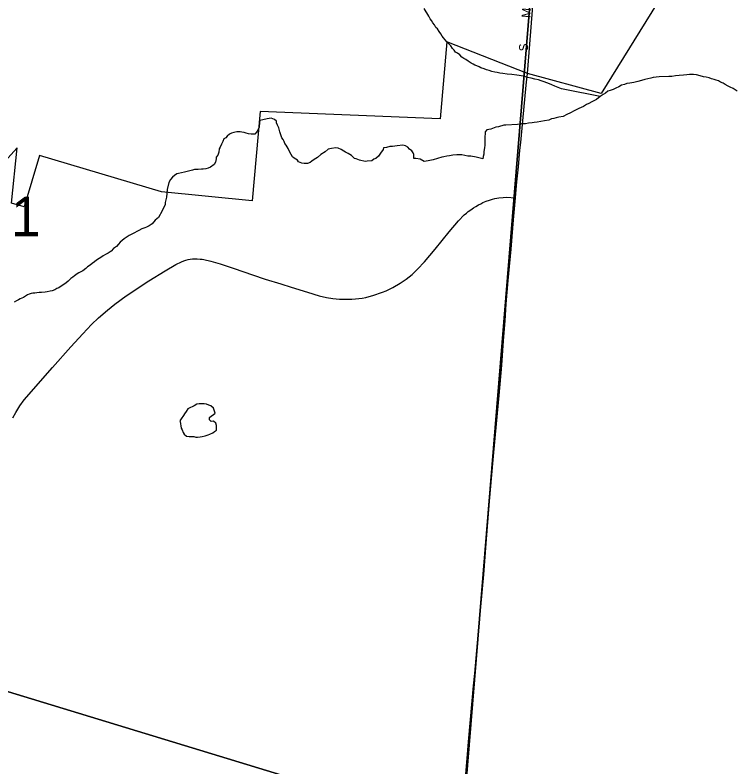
# Model space of a CAD drawing. Extents: x 1410790 to 1770854, y 448063 to 770588.
# Drawn here: x 1523133 to 1527172, y 593947 to 598152 of the extents above; entities that cross this region are included whole.
import ezdxf

# ---------------------------------------------------------------- set-up
doc = ezdxf.new("R2010")
doc.units = 0
for name, color, linetype in [('GM_X_City_Street', 7, 'Continuous'), ('GM_X_City_Street_Text', 7, 'Continuous'), ('GM_X_Corporation', 7, 'Continuous'), ('GM_X_County_Road', 7, 'Continuous'), ('GM_X_Minor_Lake', 7, 'Continuous'), ('GM_X_Minor_River', 7, 'Continuous'), ('GM_X_Section', 7, 'Continuous'), ('GM_X_Section_Text', 7, 'Continuous'), ('GM_X_Township_Road', 7, 'Continuous')]:
    doc.layers.add(name, color=color, linetype=linetype)

msp = doc.modelspace()

# ---------------------------------------------------------------- linework, layer by layer
at = {"layer": 'GM_X_City_Street'}
msp.add_lwpolyline([(1525999.4, 597825.8), (1526012.8, 597989), (1526020.3, 598085), (1526040.1, 598323.6), (1526064.5, 598621), (1526066.6, 598648.9)], dxfattribs=at)
at = {"layer": 'GM_X_Corporation'}
msp.add_lwpolyline([(1526753.1, 598265.5), (1526412.1, 597713.3), (1525999.4, 597825.8), (1525548.4, 598001.8), (1525512.3, 597571.6), (1524504.8, 597611.8), (1524459.5, 597113.5), (1523951.6, 597163.7), (1523269.7, 597366.5), (1523184.4, 597079.5), (1523113.2, 597100.8), (1523145.6, 597408.8), (1522880.8, 597121.1)], dxfattribs=at)
at = {"layer": 'GM_X_County_Road'}
for points in [[(1525932.9, 597129.9), (1525940.9, 597218.9), (1525949.3, 597303.2), (1525958, 597397.2), (1525962.1, 597438.9), (1525973.6, 597560.6), (1525993, 597759.4), (1525999.4, 597825.8)], [(1525646.9, 593818.8), (1525661.1, 593972.3), (1525671.1, 594086.5), (1525698.6, 594400.2), (1525705.4, 594468.7), (1525721.3, 594641.8), (1525756.5, 595023.8), (1525768.7, 595196.7), (1525788.5, 595432.4), (1525807.9, 595664.4), (1525818.5, 595785.3), (1525831.8, 595925.7), (1525841.6, 596023.3), (1525856.7, 596193.8), (1525866.9, 596330.6), (1525875.1, 596441.7), (1525881.6, 596536.5), (1525892, 596667.2), (1525908.2, 596843.1), (1525922.3, 597006.5), (1525932.9, 597129.9)]]:
    msp.add_lwpolyline(points, dxfattribs=at)
at = {"layer": 'GM_X_Minor_Lake'}
msp.add_lwpolyline([(1524063, 595842.4), (1524067.3, 595832.1), (1524073, 595817.9), (1524078.8, 595807.8), (1524092.6, 595797.4), (1524106.6, 595795), (1524118.6, 595794.8), (1524132.6, 595794.4), (1524144.6, 595792.1), (1524154.6, 595791.9), (1524168.6, 595793.5), (1524180.7, 595795.3), (1524196.8, 595798.9), (1524213, 595804.5), (1524223.1, 595808.3), (1524239.3, 595815.9), (1524249.5, 595823.7), (1524259.6, 595829.5), (1524259.9, 595843.5), (1524260.2, 595855.5), (1524256.5, 595869.7), (1524242.7, 595880), (1524230.7, 595878.3), (1524220.9, 595888.5), (1524221.1, 595900.6), (1524231.4, 595910.4), (1524241.5, 595916.1), (1524251.8, 595925.9), (1524242.4, 595954.2), (1524228.6, 595966.6), (1524216.7, 595970.9), (1524204.8, 595975.2), (1524190.8, 595977.5), (1524178.8, 595977.8), (1524162.8, 595978.2), (1524150.7, 595976.5), (1524134.5, 595966.8), (1524124.3, 595961.1), (1524114.2, 595957.3), (1524100, 595949.6), (1524089.7, 595933.8), (1524081.4, 595922), (1524075.1, 595912.1), (1524062.7, 595894.4), (1524054.4, 595882.5), (1524056.4, 595878.5), (1524063, 595842.4)], dxfattribs=at)
at = {"layer": 'GM_X_Minor_River'}
for points in [[(1526406.8, 597696.2), (1526208.9, 597736.4), (1526190.9, 597738.6), (1526180.9, 597742.7), (1526153, 597755), (1526137, 597761.2), (1526123.1, 597767.4), (1526093.1, 597777.7), (1526077.2, 597783.9), (1526061.2, 597790.1), (1526041.2, 597794.3), (1526021.2, 597798.5), (1526001.2, 597802.7), (1525977.3, 597811), (1525941.3, 597815.4), (1525913.3, 597819.7), (1525887.2, 597822), (1525863.2, 597824.2), (1525845.2, 597826.4), (1525831.2, 597830.6), (1525817.2, 597832.7), (1525801.3, 597836.9), (1525785.3, 597841.1), (1525771.3, 597845.2), (1525757.3, 597851.4), (1525739.3, 597857.6), (1525729.4, 597861.7), (1525717.4, 597867.8), (1525705.4, 597872), (1525695.5, 597878.1), (1525685.5, 597882.2), (1525667.6, 597894.4), (1525655.6, 597902.6), (1525643.7, 597908.7), (1525633.7, 597916.8), (1525621.8, 597929), (1525607.9, 597939.2), (1525597.9, 597945.3), (1525590, 597955.4), (1525580.1, 597965.5), (1525572.2, 597979.6), (1525560.3, 597991.8), (1525548.4, 598001.9), (1525540.5, 598014.1), (1525530.5, 598024.2), (1525522.6, 598034.3), (1525514.7, 598046.4), (1525506.8, 598060.5), (1525496.9, 598074.7), (1525487, 598082.8), (1525479.1, 598096.9), (1525471.2, 598109), (1525463.3, 598121.1), (1525455.4, 598131.2), (1525447.5, 598145.4), (1525421.8, 598187.8)], [(1527174.2, 597726.3), (1527150.3, 597740.6), (1527134.3, 597748.8), (1527122.4, 597754.9), (1527106.4, 597763.1), (1527094.5, 597771.3), (1527080.5, 597777.4), (1527068.6, 597783.6), (1527056.6, 597787.7), (1527044.6, 597791.8), (1527030.6, 597796), (1527016.6, 597800.2), (1527000.6, 597804.3), (1526984.6, 597806.5), (1526966.7, 597812.7), (1526946.7, 597816.9), (1526928.7, 597819.1), (1526918.6, 597819.2), (1526906.6, 597819.4), (1526892.6, 597817.5), (1526872.6, 597815.7), (1526848.5, 597813.9), (1526828.5, 597812.2), (1526808.4, 597808.4), (1526790.4, 597808.5), (1526736.3, 597807.1), (1526720.2, 597805.3), (1526704.2, 597803.4), (1526690.2, 597799.6), (1526674.1, 597795.7), (1526656, 597791.9), (1526638, 597786.1), (1526617.9, 597780.3)], [(1526617.9, 597780.3), (1526595.8, 597774.5), (1526573.7, 597770.7), (1526555.7, 597768.9), (1526543.6, 597763), (1526525.6, 597759.2), (1526511.5, 597751.3), (1526495.4, 597743.4), (1526479.3, 597735.6), (1526463.2, 597729.7), (1526449.2, 597725.9), (1526437.1, 597716), (1526423, 597708.1), (1526406.8, 597696.2), (1526386.7, 597680.4), (1526360.5, 597666.6), (1526344.4, 597656.8), (1526330.3, 597650.9), (1526314.2, 597641), (1526300.2, 597635.2), (1526288.1, 597629.3), (1526276, 597623.4), (1526261.9, 597615.5), (1526241.8, 597605.7), (1526219.7, 597595.9), (1526199.6, 597584.1), (1526175.5, 597580.3), (1526161.4, 597576.5), (1526147.4, 597572.6), (1526135.3, 597570.7), (1526119.3, 597564.9), (1526095.2, 597561.1), (1526075.1, 597557.3), (1526055.1, 597553.5), (1526037, 597551.7), (1526027, 597549.8), (1526005, 597548), (1525988.9, 597544.2), (1525966.9, 597544.4), (1525944.8, 597540.6), (1525878.7, 597535.3), (1525868.7, 597535.4), (1525838.5, 597527.7), (1525822.5, 597525.8), (1525794.4, 597514.1), (1525772.3, 597510.3), (1525764.2, 597498.4), (1525764.1, 597486.3), (1525762, 597474.3), (1525761.7, 597446.3), (1525761.5, 597424.2), (1525759.4, 597410.2), (1525757.3, 597400.2), (1525755.2, 597386.2), (1525755.1, 597374.1), (1525752.9, 597360.1), (1525750.8, 597348.1), (1525712.8, 597356.5), (1525682.9, 597362.9), (1525666.8, 597363), (1525632.9, 597369.4), (1525604.8, 597369.7), (1525582.8, 597367.9), (1525564.7, 597364.1), (1525548.7, 597362.2), (1525532.6, 597358.4), (1525520.6, 597356.5), (1525472.4, 597343), (1525444.3, 597337.2), (1525422.2, 597333.5), (1525400.3, 597345.7), (1525376.3, 597350), (1525364.3, 597350.1), (1525364.4, 597362.1), (1525364.5, 597372.2), (1525360.6, 597382.2), (1525352.7, 597392.3), (1525340.7, 597402.5), (1525330.8, 597412.6), (1525316.9, 597420.8), (1525302.9, 597424.9), (1525270.8, 597421.3), (1525244.7, 597417.5), (1525230.7, 597417.7), (1525210.6, 597411.9), (1525194.6, 597410), (1525192.5, 597400), (1525178.3, 597380.1), (1525166.1, 597362.2), (1525152, 597350.3), (1525140, 597346.4), (1525129.9, 597336.5), (1525103.8, 597334.8), (1525091.8, 597332.9), (1525059.8, 597341.2), (1525041.8, 597347.4), (1525031.8, 597349.5), (1525016, 597365.8), (1524996, 597378), (1524982.1, 597384.2), (1524972.1, 597390.3)], [(1524972.1, 597390.3), (1524958.2, 597400.4), (1524940.2, 597406.6), (1524928.2, 597408.8), (1524904.2, 597405), (1524884.1, 597401.2), (1524867.9, 597387.3), (1524843.8, 597371.5), (1524825.6, 597355.7), (1524807.5, 597343.8), (1524793.4, 597334), (1524783.3, 597328.1), (1524769.2, 597322.2), (1524751.2, 597322.4), (1524737.2, 597324.5), (1524719.2, 597330.7), (1524713.3, 597340.8), (1524695.4, 597351), (1524685.4, 597359.2), (1524669.7, 597385.4), (1524661.8, 597405.5), (1524650, 597423.7), (1524642.1, 597433.8), (1524638.1, 597443.9), (1524632.2, 597455.9), (1524626.3, 597466), (1524618.5, 597488.2), (1524614.6, 597498.2), (1524608.8, 597520.4), (1524600.9, 597536.5), (1524595, 597548.6), (1524595.1, 597558.6), (1524585.2, 597568.7), (1524565.2, 597575), (1524543.1, 597571.2), (1524519.1, 597565.4), (1524503, 597561.6), (1524500.9, 597551.6), (1524498.7, 597525.5), (1524490.5, 597507.5), (1524484.4, 597497.6), (1524474.3, 597485.7), (1524454.3, 597485.9), (1524438.3, 597488), (1524426.3, 597492.2), (1524414.3, 597494.3), (1524402.3, 597496.4), (1524392.3, 597498.5), (1524374.3, 597498.7), (1524356.2, 597494.9), (1524344.2, 597491), (1524332.1, 597485.1), (1524320, 597475.2), (1524311.9, 597465.3), (1524301.8, 597459.4), (1524295.7, 597445.4), (1524287.5, 597429.4), (1524281.4, 597413.4), (1524275.3, 597403.5), (1524273.1, 597385.5), (1524266.9, 597367.5), (1524258.8, 597357.5), (1524258.8, 597347.5), (1524254.6, 597329.5), (1524246.5, 597315.5), (1524226.3, 597301.7), (1524214.2, 597295.8), (1524200.2, 597292), (1524186.1, 597290.1), (1524176.1, 597290.2), (1524158.1, 597288.4), (1524136.1, 597288.6), (1524126, 597284.7), (1524103.9, 597278.9), (1524081.8, 597273.1), (1524063.8, 597269.3), (1524047.7, 597265.5), (1524037.7, 597263.6), (1524025.6, 597253.7), (1524013.5, 597245.8), (1524003.4, 597231.8), (1523993.2, 597215.9), (1523984.9, 597175.9), (1523980.5, 597133.8), (1523972.2, 597103.8), (1523972.1, 597091.8), (1523955.8, 597057.8), (1523935.4, 597020), (1523917.2, 597004.1), (1523901, 596984.2), (1523882.9, 596972.4), (1523868.8, 596966.5), (1523858.8, 596962.6), (1523842.7, 596956.8), (1523824.6, 596946.9), (1523814.5, 596941), (1523800.4, 596933.1), (1523790.4, 596929.2), (1523772.3, 596919.4), (1523754.1, 596907.5), (1523744.1, 596899.6)], [(1523744.1, 596899.6), (1523732, 596891.7), (1523721.9, 596881.8), (1523711.8, 596869.9), (1523699.6, 596858), (1523683.5, 596846.1), (1523671.4, 596832.2), (1523653.2, 596820.3), (1523639.1, 596812.5), (1523625.1, 596804.6), (1523613, 596796.7), (1523602.9, 596790.8), (1523588.8, 596780.9), (1523576.7, 596771), (1523564.6, 596763.1), (1523552.5, 596753.2), (1523538.4, 596743.3), (1523528.3, 596735.4), (1523512.2, 596721.5), (1523500.1, 596715.6), (1523490, 596709.7), (1523480, 596703.8), (1523465.8, 596693.9), (1523455.8, 596686), (1523445.7, 596678.1), (1523429.5, 596664.2), (1523419.4, 596654.3), (1523377.1, 596626.7), (1523367.1, 596622.8), (1523355, 596614.8), (1523340.9, 596609), (1523328.9, 596607.1), (1523312.8, 596603.2), (1523300.8, 596601.4), (1523280.8, 596599.6), (1523268.7, 596599.7), (1523254.7, 596597.8), (1523242.7, 596595.9), (1523232.7, 596596), (1523222.6, 596594.2), (1523212.6, 596590.2), (1523202.5, 596586.3), (1523180.4, 596572.5), (1523162.3, 596564.7), (1523152.2, 596558.8), (1523140.2, 596552.9), (1523128.1, 596547)]]:
    msp.add_lwpolyline(points, dxfattribs=at)
at = {"layer": 'GM_X_Section'}
for points in [[(1526072.4, 598935.7), (1525633.9, 593593.6), (1520311.6, 595215.7), (1520763, 600617.2)], [(1531425.6, 598513.1), (1531493.5, 598506), (1531320.1, 597039.4), (1531072, 595638.1), (1531091.6, 595622.1), (1531115.8, 595519.7), (1531165, 595358.9), (1531180.1, 595302.7), (1531189.3, 595260.5), (1531194.1, 595212.5), (1531196.1, 595192.4), (1531032, 593109.8), (1525633.9, 593593.6), (1526072.4, 598935.7)], [(1520311.6, 595215.7), (1525633.9, 593593.6), (1525156.5, 588213.3), (1519860.6, 589854.9)]]:
    msp.add_lwpolyline(points, close=True, dxfattribs=at)
at = {"layer": 'GM_X_Township_Road'}
msp.add_lwpolyline([(1523120.6, 595898.8), (1523138.1, 595929.6), (1523159.6, 595965.5), (1523183.1, 595999.8), (1523342.9, 596180.6), (1523445.6, 596295.7), (1523511.2, 596368.7), (1523560.8, 596420.8), (1523600.7, 596459.4), (1523650.1, 596502.2), (1523670.5, 596518.2), (1523690.6, 596534.8), (1523754, 596581.1), (1523786.6, 596602.8), (1523810.9, 596619.4), (1523882.3, 596665.6), (1523973.3, 596721.3), (1524032.5, 596756.1), (1524064.4, 596772), (1524077.2, 596776.9), (1524088.6, 596780.6), (1524101.6, 596784), (1524113.5, 596786.1), (1524126.7, 596787.8), (1524139.5, 596788.5), (1524152.7, 596788.5), (1524167.9, 596787.6), (1524179.1, 596786.6), (1524190, 596784.8), (1524228, 596776.1), (1524281.3, 596760.4), (1524359, 596735), (1524460.6, 596698.9), (1524532.1, 596675.6), (1524619.5, 596648.6), (1524678.4, 596630.7), (1524769.1, 596602.3), (1524834.7, 596581.6), (1524875.9, 596572.4), (1524911.9, 596566.9), (1524947.9, 596563.5), (1524973.2, 596562.3), (1524995.7, 596562.3), (1525017.1, 596563), (1525037.2, 596564.1), (1525056.1, 596565.9), (1525075.6, 596569), (1525096.4, 596573.2), (1525114.7, 596577.5), (1525134.2, 596583.8), (1525151.9, 596589.1), (1525172.1, 596595.7), (1525189.1, 596601.9), (1525209, 596610.4), (1525247.7, 596629.1), (1525287.9, 596652.1), (1525320.8, 596674.5), (1525354.2, 596701.6), (1525385.7, 596730.9), (1525423.6, 596772.2), (1525482.8, 596842.7), (1525561.8, 596939.1), (1525615.1, 597001), (1525646.6, 597033.7), (1525658.1, 597044), (1525668.7, 597052.5), (1525682.7, 597063), (1525697.4, 597073.4), (1525711.4, 597082), (1525725.4, 597089.7), (1525738.4, 597096.4), (1525751.3, 597102.8), (1525768.9, 597110.3), (1525787.4, 597117.3), (1525803.7, 597122.4), (1525818.4, 597126.3), (1525840.4, 597130.3), (1525863.6, 597132.3), (1525882.1, 597132.6), (1525932.9, 597129.9)], dxfattribs=at)

# ---------------------------------------------------------------- texts
at = {"layer": 'GM_X_City_Street_Text'}
for s, rotation, p in [('MAIN', 85.3644, (1526016.5, 598134.4)), ('S', 90, (1526003.3, 597948.8))]:
    msp.add_text(s, height=50, rotation=rotation, dxfattribs=at).set_placement(p)
at = {"layer": 'GM_X_Section_Text'}
msp.add_text('1', height=221, rotation=0, dxfattribs=at).set_placement((1523110.9, 596915.1))

doc.saveas('drawing.dxf')
